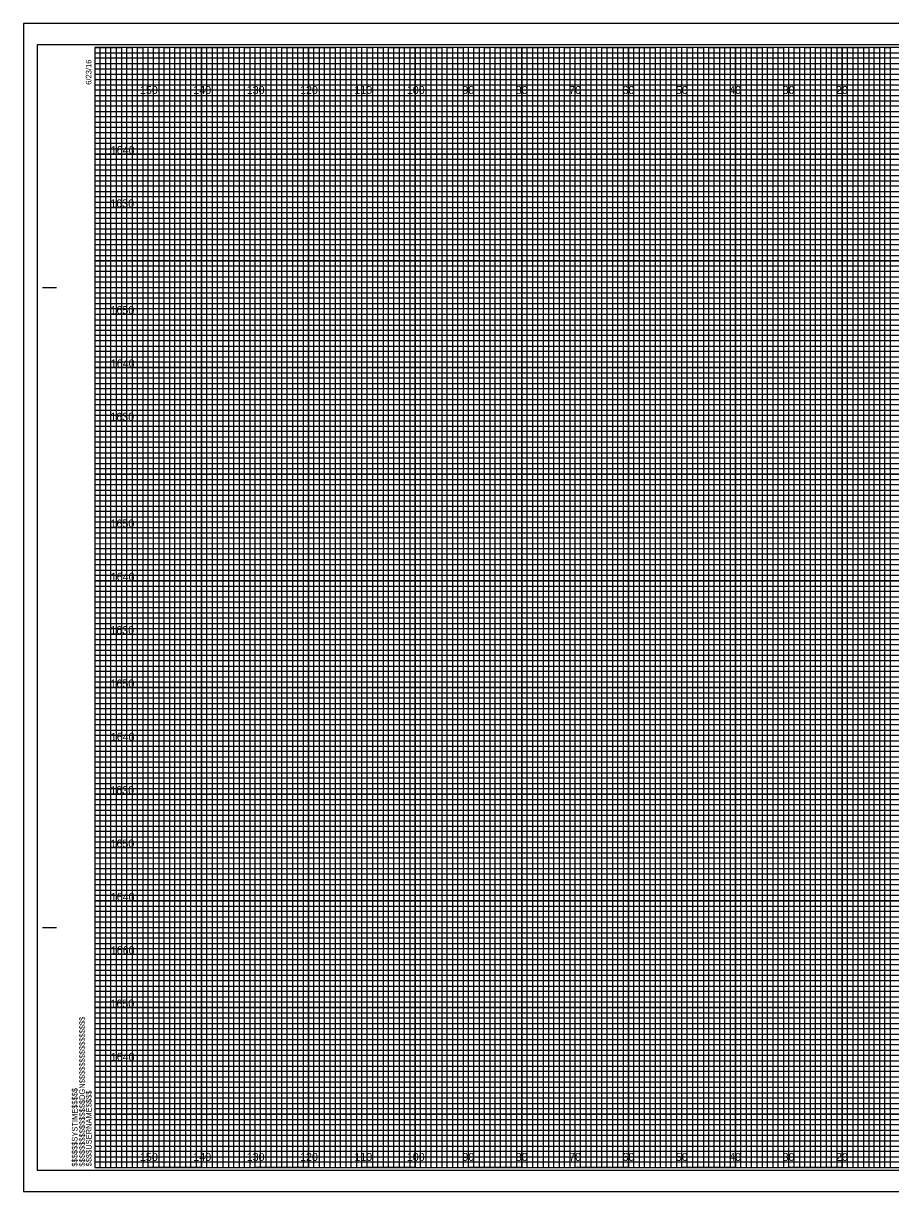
# Model space of a CAD drawing. Extents: x -423 to -87, y -23 to 1516.
# Drawn here: x -423.3 to -260.8, y 197.3 to 416.3 of the extents above; entities that cross this region are included whole.
import ezdxf

# ---------------------------------------------------------------- set-up
doc = ezdxf.new("R2010")
doc.units = 0
for name, color, linetype in [('Prop Horizontal Alignment', 7, 'Continuous'), ('Prop XS DDE', 7, 'Continuous'), ('Prop XS DDE Elevations', 7, 'Continuous'), ('Prop XS DDE Slope Text', 7, 'Continuous'), ('Prop XS Earthwork Shape', 7, 'Continuous'), ('Scratch_Level_3', 7, 'Continuous'), ('Sheet Cross Section Grid Minor 2 CELL', 7, 'Continuous'), ('Sheet Cutting Line CELL', 7, 'Continuous'), ('Sheet DOT Grid CELL', 7, 'Continuous'), ('Sheet Plot Border Inside CELL', 7, 'Continuous'), ('Sheet Plot Border Outside CELL', 7, 'Continuous')]:
    doc.layers.add(name, color=color, linetype=linetype)

msp = doc.modelspace()

# ---------------------------------------------------------------- linework, layer by layer
at = {"layer": 'Prop XS DDE'}
for points in [[(-409.86, 411.8), (-404.86, 411.8), (-404.86, 201.8), (-394.86, 201.8), (-394.86, 411.8), (-384.86, 411.8), (-384.86, 201.8), (-374.86, 201.8), (-374.86, 411.8), (-364.86, 411.8), (-364.86, 201.8), (-354.86, 201.8), (-354.86, 411.8), (-344.86, 411.8), (-344.86, 201.8), (-334.86, 201.8), (-334.86, 411.8), (-324.86, 411.8), (-324.86, 201.8), (-314.86, 201.8), (-314.86, 411.8), (-304.86, 411.8), (-304.86, 201.8), (-294.86, 201.8), (-294.86, 411.8), (-284.86, 411.8), (-284.86, 201.8), (-274.86, 201.8), (-274.86, 411.8), (-264.86, 411.8), (-264.86, 201.8), (-254.86, 201.8)], [(-409.86, 406.8), (-134.86, 406.8)], [(-409.86, 386.8), (-89.86, 386.8), (-89.86, 396.8), (-409.86, 396.8)], [(-409.86, 366.8), (-89.86, 366.8), (-89.86, 376.8), (-409.86, 376.8)], [(-409.86, 346.8), (-89.86, 346.8), (-89.86, 356.8), (-409.86, 356.8)], [(-409.86, 326.8), (-89.86, 326.8), (-89.86, 336.8), (-409.86, 336.8)], [(-409.86, 306.8), (-89.86, 306.8), (-89.86, 316.8), (-409.86, 316.8)], [(-409.86, 286.8), (-89.86, 286.8), (-89.86, 296.8), (-409.86, 296.8)], [(-409.86, 266.8), (-89.86, 266.8), (-89.86, 276.8), (-409.86, 276.8)], [(-409.86, 246.8), (-89.86, 246.8), (-89.86, 256.8), (-409.86, 256.8)], [(-409.86, 226.8), (-89.86, 226.8), (-89.86, 236.8), (-409.86, 236.8)], [(-409.86, 206.8), (-89.86, 206.8), (-89.86, 216.8), (-409.86, 216.8)]]:
    msp.add_lwpolyline(points, dxfattribs=at)
at = {"layer": 'Prop XS DDE Elevations'}
for p, q in [((-419.66, 366.8), (-417.16, 366.8)), ((-419.56, 366.8), (-417.06, 366.8)), ((-419.66, 246.8), (-417.16, 246.8)), ((-419.56, 246.8), (-417.06, 246.8)), ((-409.86, 201.8), (-409.86, 201.8)), ((-409.86, 201.8), (-409.86, 201.8)), ((-409.86, 201.8), (-409.86, 201.8)), ((-409.86, 201.8), (-409.86, 201.8)), ((-409.86, 201.8), (-409.86, 201.8)), ((-409.86, 201.8), (-409.86, 201.8)), ((-409.86, 201.8), (-409.86, 201.8))]:
    msp.add_line(p, q, dxfattribs=at)
msp.add_lwpolyline([(-89.86, 411.8), (-409.86, 411.8), (-409.86, 201.8), (-89.86, 201.8)], close=True, dxfattribs=at)
at = {"layer": 'Prop XS DDE Slope Text'}
for p, q in [((-409.86, 410.8), (-149.86, 410.8)), ((-149.86, 409.78), (-409.86, 409.78)), ((-409.86, 409.78), (-409.86, 408.8)), ((-409.86, 408.8), (-149.86, 408.8)), ((-149.86, 407.69), (-409.86, 407.69)), ((-409.86, 407.69), (-409.86, 405.8)), ((-409.86, 405.8), (-89.86, 405.8))]:
    msp.add_line(p, q, dxfattribs=at)
for points in [[(-409.86, 404.8), (-139.86, 404.8), (-89.86, 404.8), (-89.86, 403.8), (-409.86, 403.8)], [(-409.86, 402.8), (-89.86, 402.8), (-89.86, 400.8), (-409.86, 400.8)], [(-409.86, 399.8), (-89.86, 399.8), (-89.86, 398.8), (-409.86, 398.78)], [(-409.86, 397.8), (-89.86, 397.8), (-89.86, 395.8), (-409.86, 395.8)], [(-409.86, 394.8), (-89.86, 394.8), (-89.86, 393.8), (-409.86, 393.8)], [(-409.86, 392.8), (-89.86, 392.8), (-89.86, 390.8), (-409.86, 390.8)], [(-409.86, 389.8), (-89.86, 389.8), (-89.86, 388.8), (-409.86, 388.8)], [(-409.86, 387.8), (-89.86, 387.8), (-89.86, 385.8), (-409.86, 385.8)], [(-409.86, 384.8), (-89.86, 384.8), (-89.86, 383.8), (-409.86, 383.8)], [(-409.86, 382.8), (-89.86, 382.8), (-89.86, 380.8), (-409.86, 380.8)], [(-409.86, 379.8), (-89.86, 379.8), (-89.86, 378.8), (-409.86, 378.8)], [(-409.86, 377.8), (-89.86, 377.8), (-89.86, 375.75), (-89.86, 374.8), (-89.86, 373.8), (-409.86, 373.8)], [(-409.86, 375.8), (-89.86, 375.8), (-89.86, 374.8), (-409.86, 374.8)], [(-409.86, 372.8), (-89.86, 372.8), (-89.86, 370.8), (-409.86, 370.83)], [(-409.86, 370.83), (-89.86, 370.8), (-89.86, 369.8), (-409.86, 369.8)], [(-409.86, 368.8), (-89.86, 368.8), (-89.86, 367.8), (-409.86, 367.8)], [(-409.86, 365.8), (-89.86, 365.8), (-89.86, 364.8), (-409.86, 364.8)], [(-409.86, 363.8), (-89.86, 363.8), (-89.86, 362.8), (-409.86, 362.8)], [(-409.93, 360.69), (-89.86, 360.69), (-89.86, 359.68), (-409.93, 359.68)], [(-409.86, 358.8), (-89.86, 358.8), (-89.86, 357.8), (-409.86, 357.8)], [(-409.86, 355.8), (-89.86, 355.8), (-89.86, 354.8), (-409.86, 354.8)], [(-409.86, 353.8), (-89.86, 353.8), (-89.86, 352.8), (-409.86, 352.8)], [(-409.86, 350.8), (-89.86, 350.8), (-89.86, 349.8), (-409.86, 349.8)], [(-409.86, 348.8), (-89.86, 348.8), (-89.86, 347.8), (-409.86, 347.8)], [(-409.86, 345.8), (-89.86, 345.8), (-89.86, 344.8), (-409.86, 344.8)], [(-409.86, 343.8), (-89.86, 343.8), (-89.86, 342.8), (-409.86, 342.8)], [(-409.86, 340.8), (-89.86, 340.8), (-89.87, 339.78), (-409.86, 339.8)], [(-409.86, 338.8), (-89.86, 338.8), (-89.86, 337.8), (-409.86, 337.8)], [(-409.86, 335.8), (-89.86, 335.8), (-89.86, 334.8), (-409.86, 334.8)], [(-409.86, 333.8), (-89.86, 333.8), (-89.86, 332.8), (-409.86, 332.8)], [(-409.86, 330.8), (-89.86, 330.8), (-89.86, 329.8), (-409.86, 329.8)], [(-409.86, 328.8), (-89.86, 328.8), (-89.86, 327.8), (-409.86, 327.8)], [(-409.86, 325.8), (-89.86, 325.8), (-89.86, 324.8), (-409.86, 324.8)], [(-409.86, 323.8), (-89.86, 323.8), (-89.86, 322.8), (-409.86, 322.8)], [(-409.86, 320.8), (-89.86, 320.8), (-89.86, 319.8), (-409.86, 319.8)], [(-409.86, 318.79), (-89.79, 318.71), (-89.86, 317.8), (-409.86, 317.8)], [(-409.86, 315.8), (-89.86, 315.8), (-89.86, 314.8), (-409.86, 314.8)], [(-409.86, 313.8), (-89.86, 313.8), (-89.86, 312.8), (-409.86, 312.8)], [(-409.86, 310.8), (-89.86, 310.8), (-89.86, 309.8), (-409.86, 309.8)], [(-409.86, 308.8), (-89.86, 308.8), (-89.86, 307.8), (-409.86, 307.8)], [(-409.86, 305.8), (-89.86, 305.8), (-89.86, 304.8), (-409.86, 304.8)], [(-409.86, 303.8), (-89.86, 303.8), (-89.86, 302.8), (-409.86, 302.8)], [(-409.86, 300.8), (-89.86, 300.8), (-89.86, 299.8), (-409.86, 299.8)], [(-409.86, 298.8), (-89.86, 298.8), (-89.86, 297.8), (-409.86, 297.8)], [(-409.86, 295.8), (-89.86, 295.8), (-89.86, 294.8), (-409.86, 294.8)], [(-409.86, 293.8), (-89.86, 293.8), (-89.86, 292.8), (-409.86, 292.8)], [(-409.86, 290.8), (-89.86, 290.8), (-89.86, 289.8), (-409.86, 289.8)], [(-409.86, 288.8), (-89.86, 288.8), (-89.86, 287.8), (-409.86, 287.8)], [(-409.86, 285.8), (-89.86, 285.8), (-89.86, 284.8), (-409.86, 284.8)], [(-409.86, 283.8), (-89.86, 283.8), (-89.86, 282.8), (-409.86, 282.8)], [(-409.86, 280.8), (-89.86, 280.8), (-89.87, 279.78), (-409.86, 279.8)], [(-409.86, 278.8), (-89.86, 278.8), (-89.86, 277.8), (-409.86, 277.8)], [(-409.86, 275.8), (-89.86, 275.8), (-89.86, 274.8), (-409.86, 274.8)], [(-409.86, 273.8), (-89.86, 273.8), (-89.86, 272.8), (-409.86, 272.8)], [(-409.86, 270.8), (-89.86, 270.8), (-89.86, 269.8), (-409.86, 269.8)], [(-409.86, 268.8), (-89.86, 268.8), (-89.86, 267.8), (-409.86, 267.8)], [(-409.86, 265.8), (-89.86, 265.8), (-89.86, 264.8), (-409.86, 264.8)], [(-409.86, 263.8), (-89.86, 263.8), (-89.86, 262.8), (-409.86, 262.8)], [(-409.86, 260.8), (-89.86, 260.8), (-89.86, 259.8), (-409.86, 259.8)], [(-409.86, 258.79), (-89.79, 258.71), (-89.86, 257.8), (-409.86, 257.8)], [(-409.86, 255.8), (-89.86, 255.8), (-89.86, 254.8), (-409.86, 254.8)], [(-409.86, 253.8), (-89.86, 253.8), (-89.86, 252.8), (-409.86, 252.8)], [(-409.86, 250.8), (-89.86, 250.8), (-89.86, 249.8), (-409.86, 249.8)], [(-409.86, 248.8), (-89.86, 248.8), (-89.86, 247.8), (-409.86, 247.8)], [(-409.86, 245.8), (-89.86, 245.8), (-89.86, 244.8), (-409.86, 244.8)], [(-409.86, 243.8), (-89.86, 243.8), (-89.86, 242.8), (-409.86, 242.8)], [(-409.86, 240.8), (-89.86, 240.8), (-89.86, 239.8), (-409.86, 239.8)], [(-409.86, 238.8), (-89.86, 238.8), (-89.86, 237.8), (-409.86, 237.8)], [(-409.86, 235.8), (-89.86, 235.8), (-89.86, 234.8), (-409.86, 234.8)], [(-409.86, 233.8), (-89.86, 233.8), (-89.86, 232.8), (-409.86, 232.8)], [(-409.86, 230.8), (-89.86, 230.8), (-89.86, 229.8), (-409.86, 229.8)], [(-409.86, 228.8), (-89.86, 228.8), (-89.86, 227.8), (-409.86, 227.8)], [(-409.86, 225.8), (-89.86, 225.8), (-89.86, 224.8), (-409.86, 224.8)], [(-409.86, 223.8), (-89.86, 223.8), (-89.86, 222.8), (-409.86, 222.8)], [(-409.86, 220.8), (-89.86, 220.8), (-89.86, 219.8), (-409.86, 219.8)], [(-409.86, 218.8), (-89.86, 218.8), (-89.86, 217.8), (-409.86, 217.8)], [(-409.86, 215.8), (-89.86, 215.8), (-89.86, 214.8), (-409.86, 214.8)], [(-409.86, 213.8), (-89.86, 213.8), (-89.86, 212.8), (-409.86, 212.8)], [(-409.86, 210.8), (-89.86, 210.8), (-89.86, 209.8), (-409.86, 209.8)], [(-409.86, 208.8), (-89.86, 208.8), (-89.86, 207.8), (-409.86, 207.8)], [(-409.86, 205.8), (-89.86, 205.8), (-89.86, 204.8), (-409.86, 204.8)], [(-409.86, 203.8), (-89.86, 203.8), (-89.86, 202.8), (-409.86, 202.8)]]:
    msp.add_lwpolyline(points, dxfattribs=at)
at = {"layer": 'Prop XS Earthwork Shape'}
for p, q in [((-399.86, 411.8), (-409.86, 411.8)), ((-399.86, 201.8), (-399.86, 411.8)), ((-379.86, 411.8), (-389.86, 411.8)), ((-389.86, 411.8), (-389.86, 201.8)), ((-379.86, 201.8), (-379.86, 411.8)), ((-359.86, 411.8), (-369.86, 411.8)), ((-369.86, 411.8), (-369.86, 201.8)), ((-359.86, 201.8), (-359.86, 411.8)), ((-339.86, 411.8), (-349.86, 411.8)), ((-349.86, 411.8), (-349.86, 201.8)), ((-339.86, 201.8), (-339.86, 411.8)), ((-319.86, 411.8), (-329.86, 411.8)), ((-329.86, 411.8), (-329.86, 201.8)), ((-319.86, 201.8), (-319.86, 411.8)), ((-299.86, 411.8), (-309.86, 411.8)), ((-309.86, 411.8), (-309.86, 201.8)), ((-299.86, 201.8), (-299.86, 411.8)), ((-279.86, 411.8), (-289.86, 411.8)), ((-289.86, 411.8), (-289.86, 201.8)), ((-279.86, 201.8), (-279.86, 411.8)), ((-259.86, 411.8), (-269.86, 411.8)), ((-269.86, 411.8), (-269.86, 201.8)), ((-389.86, 201.8), (-399.86, 201.8)), ((-369.86, 201.8), (-379.86, 201.8)), ((-349.86, 201.8), (-359.86, 201.8)), ((-329.86, 201.8), (-339.86, 201.8)), ((-309.86, 201.8), (-319.86, 201.8)), ((-289.86, 201.8), (-299.86, 201.8)), ((-269.86, 201.8), (-279.86, 201.8))]:
    msp.add_line(p, q, dxfattribs=at)
for points in [[(-409.86, 401.8), (-89.86, 401.8), (-89.86, 391.8), (-409.86, 391.8)], [(-409.86, 381.8), (-89.86, 381.8), (-89.86, 371.8), (-409.86, 371.8)], [(-409.86, 361.8), (-89.86, 361.8), (-89.86, 351.8), (-409.86, 351.8)], [(-409.86, 341.8), (-89.86, 341.8), (-89.86, 331.8), (-409.86, 331.8)], [(-409.86, 321.8), (-89.86, 321.8), (-89.86, 311.8), (-409.86, 311.8)], [(-409.86, 301.8), (-89.86, 301.8), (-89.86, 291.8), (-409.86, 291.8)], [(-409.86, 281.8), (-89.86, 281.8), (-89.86, 271.8), (-409.86, 271.8)], [(-409.86, 261.8), (-89.86, 261.8), (-89.86, 251.8), (-409.86, 251.8)], [(-409.86, 241.8), (-89.86, 241.8), (-89.86, 231.8), (-409.86, 231.8)], [(-409.86, 221.8), (-89.86, 221.8), (-89.86, 211.8), (-409.86, 211.8)]]:
    msp.add_lwpolyline(points, dxfattribs=at)
at = {"layer": 'Sheet Cross Section Grid Minor 2 CELL'}
for points in [[(-409.86, 201.8), (-408.86, 201.8), (-408.86, 411.8), (-407.86, 411.8), (-407.86, 201.8)], [(-407.86, 201.8), (-406.86, 201.8), (-406.86, 411.8), (-405.86, 411.8), (-405.86, 201.8)], [(-404.86, 201.8), (-403.86, 201.8), (-403.86, 411.8), (-402.86, 411.8), (-402.86, 201.8)], [(-402.86, 201.8), (-401.86, 201.8), (-401.86, 411.8), (-400.86, 411.8), (-400.86, 201.8)], [(-399.86, 201.8), (-398.86, 201.8), (-398.86, 411.8), (-397.86, 411.8), (-397.86, 201.8)], [(-397.86, 201.8), (-396.86, 201.8), (-396.86, 411.8), (-395.86, 411.8), (-395.86, 201.8)], [(-394.86, 201.8), (-393.86, 201.8), (-393.86, 411.8), (-392.86, 411.8), (-392.86, 201.8)], [(-392.86, 201.8), (-391.86, 201.8), (-391.86, 411.8), (-390.86, 411.8), (-390.86, 201.8)], [(-389.86, 201.8), (-388.86, 201.8), (-388.86, 411.8), (-387.86, 411.8), (-387.86, 201.8)], [(-387.86, 201.8), (-386.86, 201.8), (-386.86, 411.8), (-385.86, 411.8), (-385.86, 201.8)], [(-384.86, 201.8), (-383.86, 201.8), (-383.86, 411.8), (-382.86, 411.8), (-382.86, 201.8)], [(-382.86, 201.8), (-381.86, 201.8), (-381.86, 411.8), (-380.86, 411.8), (-380.86, 201.8)], [(-379.86, 201.8), (-378.86, 201.8), (-378.86, 411.8), (-377.86, 411.8), (-377.86, 201.8)], [(-377.86, 201.8), (-376.86, 201.8), (-376.86, 411.8), (-375.86, 411.8), (-375.86, 201.8)], [(-374.86, 201.8), (-373.86, 201.8), (-373.86, 411.8), (-372.86, 411.8), (-372.86, 201.8)], [(-372.86, 201.8), (-371.86, 201.8), (-371.86, 411.8), (-370.86, 411.8), (-370.86, 201.8)], [(-369.86, 201.8), (-368.86, 201.8), (-368.86, 411.8), (-367.86, 411.8), (-367.86, 201.8)], [(-367.86, 201.8), (-366.86, 201.8), (-366.86, 411.8), (-365.86, 411.8), (-365.86, 201.8)], [(-364.86, 201.8), (-363.86, 201.8), (-363.86, 411.8), (-362.86, 411.8), (-362.86, 201.8)], [(-362.86, 201.8), (-361.86, 201.8), (-361.86, 411.8), (-360.86, 411.8), (-360.86, 201.8)], [(-359.86, 201.8), (-358.86, 201.8), (-358.86, 411.8), (-357.86, 411.8), (-357.86, 201.8)], [(-357.86, 201.8), (-356.86, 201.8), (-356.86, 411.8), (-355.86, 411.8), (-355.86, 201.8)], [(-354.86, 201.8), (-353.86, 201.8), (-353.86, 411.8), (-352.86, 411.8), (-352.86, 201.8)], [(-352.86, 201.8), (-351.86, 201.8), (-351.86, 411.8), (-350.86, 411.8), (-350.86, 201.8)], [(-349.86, 201.8), (-348.86, 201.8), (-348.86, 411.8), (-347.86, 411.8), (-347.86, 201.8)], [(-347.86, 201.8), (-346.86, 201.8), (-346.86, 411.8), (-345.86, 411.8), (-345.86, 201.8)], [(-344.86, 201.8), (-343.86, 201.8), (-343.86, 411.8), (-342.86, 411.8), (-342.86, 201.8)], [(-342.86, 201.8), (-341.86, 201.8), (-341.86, 411.8), (-340.86, 411.8), (-340.86, 201.8)], [(-339.86, 201.8), (-338.86, 201.8), (-338.86, 411.8), (-337.86, 411.8), (-337.86, 201.8)], [(-337.86, 201.8), (-336.86, 201.8), (-336.86, 411.8), (-335.86, 411.8), (-335.86, 201.8)], [(-334.86, 201.8), (-333.86, 201.8), (-333.86, 411.8), (-332.86, 411.8), (-332.86, 201.8)], [(-332.86, 201.8), (-331.86, 201.8), (-331.86, 411.8), (-330.86, 411.8), (-330.86, 201.8)], [(-329.86, 201.8), (-328.86, 201.8), (-328.86, 411.8), (-327.86, 411.8), (-327.86, 201.8)], [(-327.86, 201.8), (-326.86, 201.8), (-326.86, 411.8), (-325.86, 411.8), (-325.86, 201.8)], [(-324.86, 201.8), (-323.86, 201.8), (-323.86, 411.8), (-322.86, 411.8), (-322.86, 201.8)], [(-322.86, 201.8), (-321.86, 201.8), (-321.86, 411.8), (-320.86, 411.8), (-320.86, 201.8)], [(-319.86, 201.8), (-318.86, 201.8), (-318.86, 411.8), (-317.86, 411.8), (-317.86, 201.8)], [(-317.86, 201.8), (-316.86, 201.8), (-316.86, 411.8), (-315.86, 411.8), (-315.86, 201.8)], [(-314.86, 201.8), (-313.86, 201.8), (-313.86, 411.8), (-312.86, 411.8), (-312.86, 201.8)], [(-312.86, 201.8), (-311.86, 201.8), (-311.86, 411.8), (-310.86, 411.8), (-310.86, 201.8)], [(-309.86, 201.8), (-308.86, 201.8), (-308.86, 411.8), (-307.86, 411.8), (-307.86, 201.8)], [(-307.86, 201.8), (-306.86, 201.8), (-306.86, 411.8), (-305.86, 411.8), (-305.86, 201.8)], [(-304.86, 201.8), (-303.86, 201.8), (-303.86, 411.8), (-302.86, 411.8), (-302.86, 201.8)], [(-302.86, 201.8), (-301.86, 201.8), (-301.86, 411.8), (-300.86, 411.8), (-300.86, 201.8)], [(-299.86, 201.8), (-298.86, 201.8), (-298.86, 411.8), (-297.86, 411.8), (-297.86, 201.8)], [(-297.86, 201.8), (-296.86, 201.8), (-296.86, 411.8), (-295.86, 411.8), (-295.86, 201.8)], [(-294.86, 201.8), (-293.86, 201.8), (-293.86, 411.8), (-292.86, 411.8), (-292.86, 201.8)], [(-292.86, 201.8), (-291.86, 201.8), (-291.86, 411.8), (-290.86, 411.8), (-290.86, 201.8)], [(-289.86, 201.8), (-288.86, 201.8), (-288.86, 411.8), (-287.86, 411.8), (-287.86, 201.8)], [(-287.86, 201.8), (-286.86, 201.8), (-286.86, 411.8), (-285.86, 411.8), (-285.86, 201.8)], [(-284.86, 201.8), (-283.86, 201.8), (-283.86, 411.8), (-282.86, 411.8), (-282.86, 201.8)], [(-282.86, 201.8), (-281.86, 201.8), (-281.86, 411.8), (-280.86, 411.8), (-280.86, 201.8)], [(-279.86, 201.8), (-278.86, 201.8), (-278.86, 411.8), (-277.86, 411.8), (-277.86, 201.8)], [(-277.86, 201.8), (-276.86, 201.8), (-276.86, 411.8), (-275.86, 411.8), (-275.86, 201.8)], [(-274.86, 201.8), (-273.86, 201.8), (-273.86, 411.8), (-272.86, 411.8), (-272.86, 201.8)], [(-272.86, 201.8), (-271.86, 201.8), (-271.86, 411.8), (-270.86, 411.8), (-270.86, 201.8)], [(-269.86, 201.8), (-268.86, 201.8), (-268.86, 411.8), (-267.86, 411.8), (-267.86, 201.8)], [(-267.86, 201.8), (-266.86, 201.8), (-266.86, 411.8), (-265.86, 411.8), (-265.86, 201.8)], [(-264.86, 201.8), (-263.86, 201.8), (-263.86, 411.8), (-262.86, 411.8), (-262.86, 201.8)], [(-262.86, 201.8), (-261.86, 201.8), (-261.86, 411.8), (-260.86, 411.8), (-260.86, 201.8)]]:
    msp.add_lwpolyline(points, dxfattribs=at)
at = {"layer": 'Sheet Cutting Line CELL'}
for p, q in [((-86.56, 416.3), (-423.26, 416.3)), ((-423.26, 416.3), (-423.26, 197.3)), ((-423.26, 197.3), (-86.56, 197.3))]:
    msp.add_line(p, q, dxfattribs=at)
at = {"layer": 'Sheet DOT Grid CELL'}
for p, q in [((-399.86, 201.8), (-399.86, 411.8)), ((-389.86, 201.8), (-389.86, 411.8)), ((-379.86, 201.8), (-379.86, 411.8)), ((-369.86, 201.8), (-369.86, 411.8)), ((-359.86, 201.8), (-359.86, 411.8)), ((-349.86, 201.8), (-349.86, 411.8)), ((-339.86, 201.8), (-339.86, 411.8)), ((-329.86, 201.8), (-329.86, 411.8)), ((-319.86, 201.8), (-319.86, 411.8)), ((-309.86, 201.8), (-309.86, 411.8)), ((-299.86, 201.8), (-299.86, 411.8)), ((-289.86, 201.8), (-289.86, 411.8)), ((-279.86, 201.8), (-279.86, 411.8)), ((-269.86, 201.8), (-269.86, 411.8)), ((-409.86, 401.8), (-89.86, 401.8)), ((-409.86, 391.8), (-89.86, 391.8)), ((-409.86, 381.8), (-89.86, 381.8)), ((-409.86, 371.8), (-89.86, 371.8)), ((-409.86, 361.8), (-89.86, 361.8)), ((-409.86, 351.8), (-89.86, 351.8)), ((-409.86, 341.8), (-89.86, 341.8)), ((-409.86, 331.8), (-89.86, 331.8)), ((-409.86, 321.8), (-89.86, 321.8)), ((-409.86, 311.8), (-89.86, 311.8)), ((-409.86, 301.8), (-89.86, 301.8)), ((-409.86, 291.8), (-89.86, 291.8)), ((-409.86, 281.8), (-89.86, 281.8)), ((-409.86, 271.8), (-89.86, 271.8)), ((-409.86, 261.8), (-89.86, 261.8)), ((-409.86, 251.8), (-89.86, 251.8)), ((-409.86, 241.8), (-89.86, 241.8)), ((-409.86, 231.8), (-89.86, 231.8)), ((-409.86, 221.8), (-89.86, 221.8)), ((-409.86, 211.8), (-89.86, 211.8))]:
    msp.add_line(p, q, dxfattribs=at)
at = {"layer": 'Sheet Plot Border Inside CELL'}
msp.add_lwpolyline([(-420.66, 201.3), (-87.46, 201.3), (-87.46, 412.3), (-420.66, 412.3)], close=True, dxfattribs=at)
at = {"layer": 'Sheet Plot Border Outside CELL'}
msp.add_lwpolyline([(-423.26, 197.3), (-86.56, 197.3), (-86.56, 416.3), (-423.26, 416.3)], close=True, dxfattribs=at)

# ---------------------------------------------------------------- texts
at = {"layer": 'Prop Horizontal Alignment'}
for s, p in [('1640', (-406.89, 391.8)), ('1630', (-406.98, 381.8)), ('1650', (-406.94, 361.8)), ('1640', (-406.89, 351.8)), ('1630', (-406.98, 341.8)), ('1650', (-406.94, 321.8)), ('1640', (-406.89, 311.8)), ('1630', (-406.98, 301.8)), ('1650', (-406.94, 291.8)), ('1640', (-406.89, 281.8)), ('1630', (-406.98, 271.8)), ('1650', (-406.94, 261.8)), ('1640', (-406.89, 251.8)), ('1660', (-406.89, 241.8)), ('1650', (-406.94, 231.8)), ('1640', (-406.89, 221.8))]:
    msp.add_text(s, height=1.5, dxfattribs=at).set_placement(p)
at = {"layer": 'Prop XS DDE Elevations'}
for s, p in [('6/23/16', (-410.51, 404.8)), ('$$$$$$$$$$$$$$$$DGN$$$$$$$$$$$$$$$$', (-411.74, 201.98)), ('$$$$$$SYSTIME$$$$$', (-413.12, 201.98)), ('$$$$USERNAME$$$$', (-410.48, 202.03))]:
    msp.add_text(s, height=1.05, rotation=90, dxfattribs=at).set_placement(p)
at = {"layer": 'Scratch_Level_3'}
for s, p in [('150', (-401.42, 403.05)), ('140', (-391.42, 403.05)), ('130', (-381.42, 403.05)), ('120', (-371.42, 403.05)), ('110', (-361.24, 403.05)), ('100', (-351.42, 403.05)), ('90', (-341.01, 403.05)), ('80', (-331.01, 403.05)), ('70', (-321.01, 403.05)), ('60', (-311.01, 403.05)), ('50', (-301.01, 403.05)), ('40', (-291.01, 403.05)), ('30', (-281.01, 403.05)), ('20', (-271.01, 403.05)), ('150', (-401.42, 203.05)), ('140', (-391.42, 203.05)), ('130', (-381.42, 203.05)), ('120', (-371.42, 203.05)), ('110', (-361.24, 203.05)), ('100', (-351.42, 203.05)), ('90', (-341.01, 203.05)), ('80', (-331.01, 203.05)), ('70', (-321.01, 203.05)), ('60', (-311.01, 203.05)), ('50', (-301.01, 203.05)), ('40', (-291.01, 203.05)), ('30', (-281.01, 203.05)), ('20', (-271.01, 203.05))]:
    msp.add_text(s, height=1.5, dxfattribs=at).set_placement(p)

doc.saveas('drawing.dxf')
